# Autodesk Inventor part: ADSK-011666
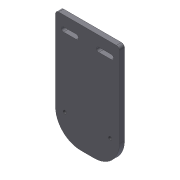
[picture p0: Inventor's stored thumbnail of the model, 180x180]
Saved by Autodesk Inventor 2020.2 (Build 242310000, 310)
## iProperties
Created: 2000-02
Part Number: ADSK-011666
Material: Pearson HRS
Document SubType Name: Modeling
Designer: sspink
Density: 7.83 g/cm^3
Appearance: Métal - Acier
Mass: 2012.07 g
Surface Area: 597.562 cm^2
Volume: 256.969 cm^3
Control State: 0
Master: False
Checked Out: False
Shininess: 0.0
Length Units: 11269
Angle Units: 11279
Time Units: 11290
Mass Units: 11283
Length Display Precision: 3
Angle Display Precision: 2
Compacted: True
Cutlength: 23.25
Material Desc: Material Description goes here
Material_Number: Pearson
Dimensions: 216x10x127 mm
Mass: 2,012 kg
VLT_Material: Pearson HRS
Density: 0.0
Volumn: 0.0
Area: 0.0
PropertySet Name: Model Information
Author: sspink
Revision Number: -
Title: ADSK-011666
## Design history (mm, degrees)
node "Solide1"
  node "Extrusion1" dims "d2" = 10, "d3" = 0
  node "Fillet1" dims "d11" = 50
  node "Extrusion2" dims "d17" = 9.525, "d18" = 0
  node "Fillet2" dims "d19" = 6
  node "Hole3" dims "d32" = 6.647, "d33" = 9.525, "d34" = 6.35, "d35" = 60 deg, "d36" = 19.05, "d37" = 118 deg, "d42" = 16
sketch "Sketch1"
  geometry: L1 (-63.5, -108)-(63.5, -108); L2 (63.5, -108)-(63.5, 108); L3 (63.5, 108)-(-63.5, 108); L4 (-63.5, 108)-(-63.5, -108); 3 further points
  constraints: 8 end point, 2 midpoint, 2 parallel, 1 horizontal, 1 horizontal alignment, 1 perpendicular, 1 vertical alignment
  dimensions: "d0" = 127 distance between parallel lines of L2 L4; "d1" = 216 distance between parallel lines of L1 L3
sketch "Sketch3"
  geometry: L1 (-63.5, 108)-(63.5, 108) reference; L2 (-47.5, 87.5)-(-22.5, 87.5); L3 (-22.5, 87.5)-(-22.5, 78.5); L4 (-22.5, 78.5)-(-47.5, 78.5); L5 (-47.5, 78.5)-(-47.5, 87.5); L6 (22.5, 87.5)-(47.5, 87.5); L7 (47.5, 87.5)-(47.5, 78.5); L8 (47.5, 78.5)-(22.5, 78.5); L9 (22.5, 78.5)-(22.5, 87.5); L10 (-22.5, 83)-(22.5, 83); A1 r 4.5 centre (-47.5, 83) between (-47.5, 87.5) and (-47.5, 78.5); A2 r 4.5 centre (-22.5, 83) between (-22.5, 78.5) and (-22.5, 87.5); A3 r 4.5 centre (22.5, 83) between (22.5, 87.5) and (22.5, 78.5); A4 r 4.5 centre (47.5, 83) between (47.5, 78.5) and (47.5, 87.5); 2 further points
  constraints: 18 end point, 8 point on circle, 4 centre point, 4 parallel, 4 tangent, 3 perpendicular, 2 horizontal, 2 midpoint, 1 collinear, 1 equal radius, 1 horizontal alignment, 1 vertical alignment
  dimensions: "d12" = 25 distance between parallel lines of L3 L5; "d13" = 9 distance between parallel lines of L4 L2; "d15" = 25 distance from line of A1.centre L1; "d39" = 45 distance of L10.start L10.end
sketch "Sketch5"
  geometry: L1 (-57.5, 108)-(57.5, 108) reference; L2 (13.5, -108)-(-13.5, -108) reference; L3 (0, 108)-(0, -108); L4 (-45, -58)-(45, -58); 2 further points
  constraints: 4 end point, 3 midpoint, 1 coincident, 1 horizontal, 1 point on line
  dimensions: "d40" = 50 distance between parallel lines of L4 L2; "d41" = 90 distance of L4.start L4.end
node "Corps solides"
node "Corps surfaciques"
